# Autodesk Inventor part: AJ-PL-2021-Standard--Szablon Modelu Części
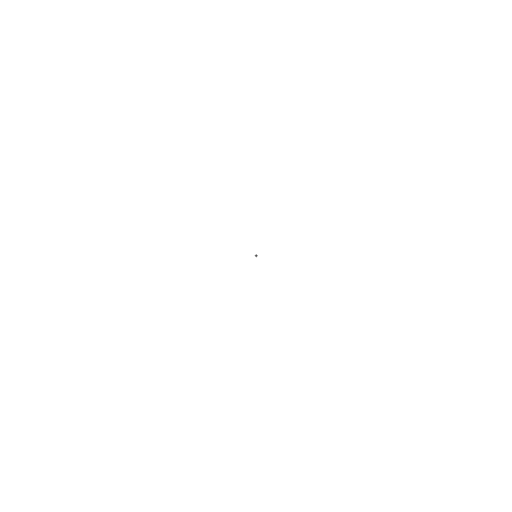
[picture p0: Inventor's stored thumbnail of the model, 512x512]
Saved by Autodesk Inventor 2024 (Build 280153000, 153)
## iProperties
Company: ATC
Created: 2023-03
Part Number: AJ-PL-2021-Standard--Szablon Modelu Części
Material: Kurs-AJ
Document SubType Name: Modeling
Density: 1 g/cm^3
Appearance: Kurs-AJ
Checked By: A.J.
Engr Approved By: Andrzej Jaskulski
Mfg Approved By: Andrzej Jaskulski
Designer: Andrzej Jaskulski
Authority: A.J.
Title: A.J.: Kurs R2024-MEP
Author: Andrzej Jaskulski
Revision Number: 1/24
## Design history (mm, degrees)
